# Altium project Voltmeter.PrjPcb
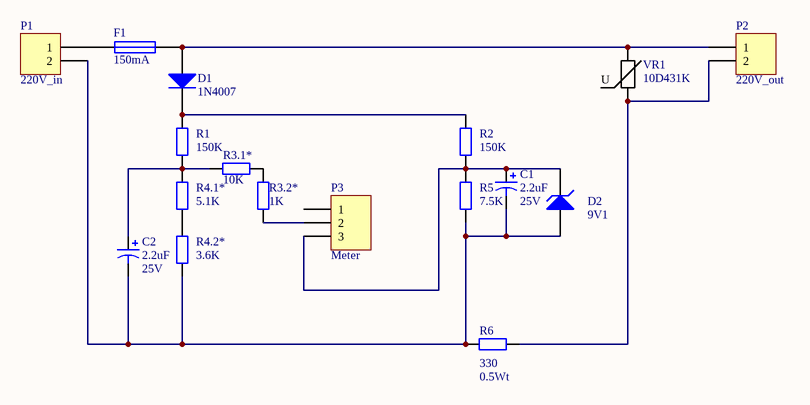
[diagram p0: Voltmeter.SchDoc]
1 sheet, 17 parts. Net scope: global (net labels, ports and power ports of the same name join across sheets).

## Sheet Voltmeter.SchDoc
size A4; PageSetup: Record=PageOptions|CenterHorizontal=True|CenterVertical=True|PrintScale=1.00|XCorrection=1.00|YCorrection=1.00|PrintKind=1|BorderSize=5000000|LeftOffset=0|BottomOffset=0|Orientation=2|PaperLength=1000|PaperWidth=1000|Scale=100|PaperSource=1|PrintQuality=300|MediaType=1|DitherType=10|PaperKind=A4|PrintScaleMode=1

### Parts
C1  25V  value 2.2uF  [RB7.6-15]
C2  25V  value 2.2uF  [RB7.6-15]
D1  1N4007  [DO-41]
D2  9V1  [DIODE-0.7]
F1  150mA  [PIN-W2/E2.8]
P1  220V_in  [HDR1X2]
P2  220V_out  [HDR1X2]
P3  Meter  [HDR1X3]
R1  value 150K  [AXIAL-0.4]  (hidden comment: Res2)
R2  value 150K  [AXIAL-0.4]  (hidden comment: Res2)
R3.1*  value 10K  [AXIAL-0.4]  (hidden comment: Res2)
R3.2*  value 1K  [AXIAL-0.4]  (hidden comment: Res2)
R4.1*  value 5.1K  [AXIAL-0.4]  (hidden comment: Res2)
R4.2*  value 3.6K  [AXIAL-0.4]  (hidden comment: Res2)
R5  value 7.5K  [AXIAL-0.4]  (hidden comment: Res2)
R6  0.5Wt  value 330  [AXIAL-0.4]
VR1  10D431K

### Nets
NetC1_1: C1.1 D2.2(K) P3.3 R2.1 R5.2
NetC1_2: C1.2 C2.2 D2.1(A) P1.2 R4.2*.1 R5.1 R6.1
NetC2_1: C2.1 R1.1 R3.1*.2 R4.1*.2
NetD1_1: D1.1(A) F1.2 P2.1 VR1.1
NetD1_2: D1.2(K) R1.2 R2.2
NetF1_1: F1.1 P1.1
NetP2_2: P2.2 R6.2 VR1.2
NetP3_2: P3.2 R3.2*.2
NetR3.1*_1: R3.1*.1 R3.2*.1
NetR4.1*_1: R4.1*.1 R4.2*.2

Not connected (* = marked no-connect by the designer): P3 1

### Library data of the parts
C1 C2 = Cap Pol1: Polarized Capacitor (Radial)
D1 = Diode 1N4007: 1 Amp General Purpose Rectifier
D2 = D Zener: Zener Diode
F1 = Fuse 1: Fuse
P1 P2 = Header 2: Header, 2-Pin
P3 = Header 3: Header, 3-Pin
R1 R2 R3.1* R3.2* R4.1* R4.2* R5 R6 = Res2: Resistor
VR1 = Varistor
